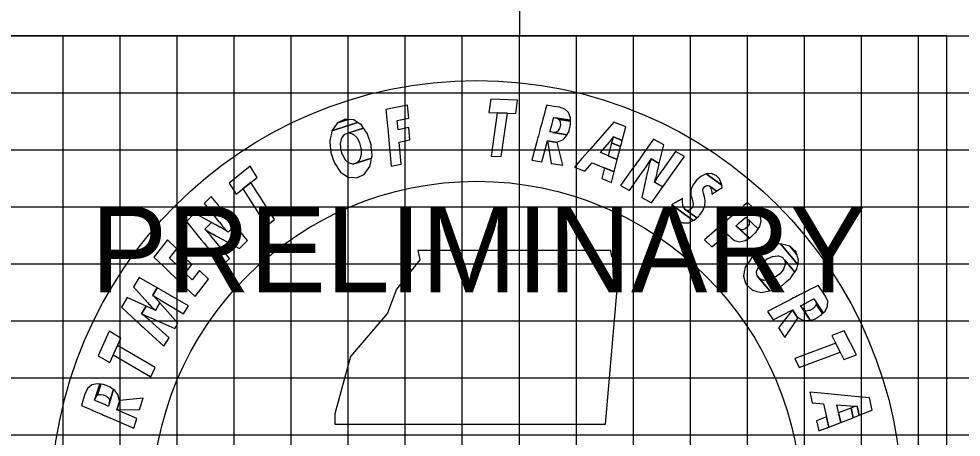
# Model space of a CAD drawing. Extents: x -10 to 342, y -5 to 215.
# Drawn here: x 313.22 to 329.75, y 194.96 to 202.3 of the extents above; entities that cross this region are included whole.
import ezdxf

# ---------------------------------------------------------------- set-up
doc = ezdxf.new("R2010")
doc.units = 0
for name, color, linetype in [('SHEET_CONSULTANT_STAMP', 7, 'Continuous'), ('SHEET_LOGO', 7, 'Continuous'), ('SHEET_LOGO_BG', 7, 'Continuous'), ('SHEET_PRELIM', 7, 'Continuous'), ('SHEET_PROJ_NUMBER', 7, 'Continuous'), ('XS_SHEET_MAJOR_GRIDS', 7, 'Continuous'), ('XS_SHEET_MEDIUM_GRIDS', 7, 'Continuous'), ('XS_SHEET_MINOR_GRIDS', 7, 'Continuous')]:
    doc.layers.add(name, color=color, linetype=linetype)

msp = doc.modelspace()

# ---------------------------------------------------------------- linework, layer by layer
at = {"layer": 'SHEET_CONSULTANT_STAMP'}
msp.add_lwpolyline([(313, 185.5), (329.5, 185.5), (329.5, 202), (313, 202)], close=True, dxfattribs=at)
at = {"layer": 'SHEET_LOGO'}
for points in [[(321.499, 200.886), (321.465, 200.655), (321.937, 200.637), (321.97, 200.868)], [(319.717, 200.101), (319.753, 199.713), (319.928, 199.748), (319.892, 200.136), (320.082, 200.175), (320.062, 200.389), (319.872, 200.351), (319.856, 200.515), (320.06, 200.556), (320.039, 200.785), (319.661, 200.709), (319.682, 200.48), (319.697, 200.315)], [(322.318, 200.184), (322.218, 199.815), (322.394, 199.787), (322.493, 200.157), (322.665, 200.129), (322.662, 200.142), (322.702, 200.15), (322.761, 200.176), (322.824, 200.238), (322.837, 200.264), (322.535, 200.312), (322.537, 200.319), (322.544, 200.345), (322.553, 200.38), (322.557, 200.395), (322.574, 200.456), (322.574, 200.456), (322.586, 200.501), (322.585, 200.501), (322.589, 200.512), (322.598, 200.548), (322.602, 200.563), (322.603, 200.566), (322.897, 200.519), (322.896, 200.561), (322.862, 200.652), (322.797, 200.714), (322.702, 200.745), (322.605, 200.761), (322.478, 200.781), (322.478, 200.781), (322.474, 200.765), (322.461, 200.715), (322.439, 200.634), (322.428, 200.594), (322.427, 200.591), (322.423, 200.576), (322.413, 200.54), (322.41, 200.529), (322.398, 200.484), (322.382, 200.423), (322.378, 200.408), (322.368, 200.373), (322.361, 200.347), (322.359, 200.339), (322.352, 200.313), (322.334, 200.243), (322.324, 200.209), (322.321, 200.197)], [(318.771, 200.416), (318.713, 200.334), (319.16, 200.481), (319.097, 200.523), (318.996, 200.531), (318.809, 200.47)], [(318.946, 200.535), (318.81, 200.47), (318.996, 200.531), (318.946, 200.535)], [(321.614, 200.649), (321.504, 199.89), (321.683, 199.883), (321.793, 200.643)], [(322.635, 200.304), (322.59, 200.303), (322.837, 200.264), (322.841, 200.271), (322.854, 200.296), (322.872, 200.329), (322.875, 200.345), (322.889, 200.406), (322.899, 200.451), (322.898, 200.463), (322.898, 200.5), (322.7, 200.532), (322.719, 200.491), (322.719, 200.48), (322.721, 200.433), (322.704, 200.372), (322.695, 200.357), (322.674, 200.325)], [(322.662, 200.554), (322.7, 200.532), (322.898, 200.5), (322.897, 200.517), (322.897, 200.519), (322.629, 200.562)], [(319.098, 199.512), (319.147, 199.508), (319.283, 199.573), (319.32, 199.625), (319.379, 199.708), (319.394, 199.783), (319.409, 199.853), (319.083, 199.745), (319.082, 199.746), (319.018, 199.762), (319.01, 199.763), (319.008, 199.765), (318.945, 199.823), (318.944, 199.825), (318.942, 199.829), (318.896, 199.914), (318.895, 199.917), (318.894, 199.922), (318.869, 200.012), (318.868, 200.017), (318.868, 200.022), (318.864, 200.12), (318.865, 200.124), (318.866, 200.125), (318.888, 200.212), (318.888, 200.212), (318.896, 200.222), (318.94, 200.274), (319.009, 200.297), (319.266, 200.381), (319.23, 200.435), (319.16, 200.481), (318.713, 200.334), (318.698, 200.26), (318.683, 200.19), (318.683, 200.189), (318.675, 200.15), (318.676, 200.143), (318.676, 200.142), (318.683, 200.065), (318.683, 200.064), (318.683, 200.06), (318.692, 199.964), (318.692, 199.96), (318.693, 199.954), (318.722, 199.866), (318.724, 199.861), (318.725, 199.858), (318.756, 199.768), (318.757, 199.764), (318.758, 199.762), (318.802, 199.698), (318.804, 199.696), (318.806, 199.692), (318.827, 199.662), (318.827, 199.661), (318.863, 199.608), (318.932, 199.561), (318.996, 199.519)], [(319.194, 199.819), (319.151, 199.768), (319.409, 199.853), (319.417, 199.893), (319.417, 199.897), (319.417, 199.9), (319.41, 199.976), (319.41, 199.978), (319.41, 199.978), (319.409, 199.982), (319.401, 200.08), (319.401, 200.083), (319.4, 200.089), (319.37, 200.177), (319.369, 200.182), (319.367, 200.186), (319.337, 200.275), (319.336, 200.279), (319.335, 200.28), (319.292, 200.344), (319.291, 200.345), (319.287, 200.351), (319.267, 200.381), (319.266, 200.381), (319.009, 200.297), (319.009, 200.296), (319.07, 200.279), (319.082, 200.276), (319.083, 200.276), (319.148, 200.218), (319.148, 200.217), (319.15, 200.213), (319.196, 200.13), (319.197, 200.125), (319.198, 200.12), (319.222, 200.03), (319.223, 200.025), (319.223, 200.021), (319.226, 199.922), (319.225, 199.918), (319.224, 199.915), (319.202, 199.829), (319.199, 199.825)], [(323.099, 199.846), (322.968, 199.697), (323.148, 199.622), (323.279, 199.771), (323.662, 199.612), (323.718, 199.828), (323.426, 199.95), (323.579, 200.133), (323.582, 200.136), (323.616, 200.181), (323.617, 200.182), (323.651, 200.229), (323.805, 200.165), (323.866, 200.401), (323.66, 200.487), (323.492, 200.295), (323.453, 200.25), (323.452, 200.249), (323.414, 200.206), (323.411, 200.203), (323.253, 200.022)], [(323.632, 200.174), (323.617, 200.122), (323.776, 200.055), (323.79, 200.108), (323.791, 200.109), (323.805, 200.165), (323.651, 200.229), (323.632, 200.175)], [(323.975, 199.652), (323.776, 199.373), (323.931, 199.285), (324.128, 199.566), (324.128, 199.566), (324.177, 199.635), (324.183, 199.644), (324.222, 199.699), (324.224, 199.702), (324.262, 199.758), (324.268, 199.767), (324.31, 199.839), (324.455, 199.757), (324.533, 200.088), (324.356, 200.187), (324.166, 199.92), (324.117, 199.852), (324.111, 199.843), (324.071, 199.787), (324.069, 199.785), (324.03, 199.73), (324.024, 199.721)], [(322.493, 200.157), (322.561, 199.761), (322.762, 199.729), (322.665, 200.129)], [(323.616, 200.118), (323.556, 199.896), (323.718, 199.828), (323.775, 200.051), (323.776, 200.055), (323.617, 200.122)], [(319.151, 199.768), (319.083, 199.745), (319.409, 199.853), (319.409, 199.853)], [(324.226, 199.511), (324.146, 199.164), (324.317, 199.068), (324.516, 199.347), (324.369, 199.43), (324.395, 199.512), (324.399, 199.522), (324.415, 199.59), (324.416, 199.594), (324.432, 199.662), (324.434, 199.673), (324.455, 199.757), (324.31, 199.839), (324.284, 199.757), (324.28, 199.747), (324.264, 199.679), (324.263, 199.676), (324.248, 199.607), (324.245, 199.596)], [(324.411, 199.502), (324.369, 199.43), (324.516, 199.347), (324.564, 199.416), (324.571, 199.425), (324.61, 199.48), (324.612, 199.483), (324.651, 199.538), (324.658, 199.547), (324.897, 199.883), (324.741, 199.97), (324.503, 199.634), (324.496, 199.625), (324.457, 199.57), (324.455, 199.567), (324.417, 199.512)], [(316.91, 199.416), (317.035, 199.22), (317.404, 199.514), (317.279, 199.711)], [(323.495, 199.682), (323.447, 199.497), (323.615, 199.428), (323.662, 199.612)], [(324.96, 198.931), (324.911, 198.95), (325.112, 198.804), (325.122, 198.813), (325.128, 198.818), (325.145, 198.831), (325.152, 198.841), (325.162, 198.854), (325.184, 198.883), (325.209, 198.915), (325.213, 198.92), (325.225, 198.946), (325.239, 198.978), (325.254, 199.01), (325.255, 199.022), (325.261, 199.093), (325.26, 199.103), (325.247, 199.175), (325.228, 199.239), (325.228, 199.24), (325.22, 199.284), (325.227, 199.324), (325.23, 199.328), (325.251, 199.353), (325.251, 199.353), (325.252, 199.355), (325.256, 199.357), (325.29, 199.375), (325.305, 199.372), (325.305, 199.372), (325.329, 199.368), (325.459, 199.273), (325.502, 199.3), (325.555, 199.333), (325.55, 199.377), (325.277, 199.577), (325.244, 199.561), (325.184, 199.532), (325.148, 199.5), (325.14, 199.493), (325.135, 199.489), (325.108, 199.466), (325.105, 199.463), (325.103, 199.461), (325.084, 199.434), (325.082, 199.431), (325.06, 199.401), (325.042, 199.376), (325.042, 199.375), (325.028, 199.335), (325.011, 199.285), (325.011, 199.277), (325.011, 199.2), (325.015, 199.185), (325.029, 199.132), (325.044, 199.078), (325.049, 199.04), (325.05, 199.032), (325.039, 198.989), (325.015, 198.962), (325.005, 198.949), (324.991, 198.944), (324.969, 198.934)], [(325.31, 199.579), (325.277, 199.576), (325.55, 199.377), (325.546, 199.405), (325.519, 199.474), (325.515, 199.483), (325.454, 199.55), (325.454, 199.55), (325.391, 199.574), (325.371, 199.582)], [(317.152, 199.313), (317.564, 198.666), (317.705, 198.778), (317.292, 199.425)], [(325.374, 199.263), (325.377, 199.22), (325.407, 199.239), (325.409, 199.241), (325.413, 199.243), (325.444, 199.262), (325.45, 199.266), (325.449, 199.266), (325.459, 199.273), (325.329, 199.368), (325.358, 199.333), (325.361, 199.323), (325.373, 199.272), (325.374, 199.267)], [(316.834, 198.614), (316.893, 198.554), (317.011, 198.674), (316.958, 198.739), (316.951, 198.747), (316.908, 198.8), (316.906, 198.802), (316.863, 198.855), (316.856, 198.863), (316.595, 199.182), (316.469, 199.055), (316.731, 198.736), (316.738, 198.728), (316.781, 198.676), (316.783, 198.673), (316.827, 198.622)], [(324.722, 198.8), (324.79, 198.746), (324.803, 198.741), (324.874, 198.715), (324.902, 198.716), (324.972, 198.72), (324.991, 198.729), (325.052, 198.759), (324.673, 199.036), (324.669, 198.965), (324.673, 198.94), (324.683, 198.877), (324.701, 198.841)], [(324.688, 199.044), (324.673, 199.036), (325.052, 198.759), (325.068, 198.766), (325.112, 198.804), (324.911, 198.95), (324.888, 198.984), (324.875, 199.003), (324.87, 199.032), (324.867, 199.049), (324.864, 199.072), (324.864, 199.117), (324.865, 199.142), (324.845, 199.131), (324.81, 199.112), (324.794, 199.103), (324.782, 199.097), (324.762, 199.085), (324.755, 199.081), (324.742, 199.074)], [(325.509, 198.648), (325.246, 198.42), (325.376, 198.299), (325.639, 198.527), (325.674, 198.495), (325.715, 198.457), (325.775, 198.409), (325.858, 198.385), (325.96, 198.408), (326.032, 198.45), (325.799, 198.667), (325.799, 198.667), (325.803, 198.67), (325.821, 198.685), (325.824, 198.688), (325.854, 198.715), (325.897, 198.751), (325.919, 198.771), (325.935, 198.784), (325.96, 198.806), (325.969, 198.814), (325.971, 198.815), (326.19, 198.611), (326.217, 198.651), (326.243, 198.751), (326.227, 198.842), (326.167, 198.921), (326.095, 198.988), (326.001, 199.075), (326.001, 199.075), (325.988, 199.064), (325.946, 199.027), (325.877, 198.968), (325.841, 198.936), (325.839, 198.935), (325.83, 198.927), (325.805, 198.905), (325.789, 198.892), (325.767, 198.872), (325.725, 198.836), (325.694, 198.809), (325.691, 198.806), (325.674, 198.791), (325.669, 198.788), (325.669, 198.788), (325.609, 198.735), (325.543, 198.678), (325.514, 198.653), (325.509, 198.649)], [(316.575, 198.232), (316.793, 197.966), (316.918, 198.094), (316.699, 198.357), (316.699, 198.357), (316.645, 198.422), (316.638, 198.43), (316.595, 198.482), (316.593, 198.485), (316.549, 198.536), (316.542, 198.545), (316.483, 198.604), (316.6, 198.722), (316.302, 198.885), (316.159, 198.74), (316.367, 198.486), (316.42, 198.421), (316.427, 198.413), (316.47, 198.36), (316.472, 198.358), (316.515, 198.306), (316.522, 198.297)], [(316.777, 198.437), (317.091, 198.268), (317.229, 198.408), (317.011, 198.674), (316.893, 198.554), (316.821, 198.6), (316.812, 198.607), (316.751, 198.64), (316.748, 198.642), (316.686, 198.675), (316.676, 198.681), (316.6, 198.722), (316.483, 198.604), (316.555, 198.558), (316.564, 198.552), (316.626, 198.518), (316.628, 198.516), (316.69, 198.483), (316.7, 198.478)], [(325.917, 198.596), (325.875, 198.603), (326.037, 198.453), (326.057, 198.465), (326.061, 198.467), (326.09, 198.495), (326.13, 198.534), (326.152, 198.554), (326.163, 198.571), (326.182, 198.599), (326.189, 198.609), (326.19, 198.611), (325.994, 198.793), (326.017, 198.769), (326.034, 198.737), (326.033, 198.693), (326.022, 198.675), (326.007, 198.649), (325.964, 198.612), (325.921, 198.597)], [(325.842, 198.627), (325.812, 198.655), (326.032, 198.45), (326.032, 198.45), (326.037, 198.453), (325.875, 198.603)], [(316.151, 197.577), (316.311, 197.423), (316.547, 197.727), (316.387, 197.881), (316.26, 197.718), (316.14, 197.833), (316.258, 197.985), (316.102, 198.135), (315.984, 197.984), (315.866, 198.097), (315.992, 198.26), (315.826, 198.42), (315.59, 198.116), (315.756, 197.956), (315.874, 197.843), (316.031, 197.692)], [(323.761, 198.093), (323.623, 198.119), (323.606, 198.231), (320.218, 198.231), (320.252, 198.067), (319.848, 197.551), (319.685, 197.13), (319.04, 196.373), (318.764, 195.367), (318.764, 195.186), (323.512, 195.186)], [(325.961, 197.684), (325.977, 197.636), (326.088, 197.534), (326.15, 197.52), (326.249, 197.496), (326.324, 197.51), (326.394, 197.523), (326.173, 197.785), (326.173, 197.786), (326.163, 197.851), (326.162, 197.859), (326.163, 197.862), (326.193, 197.942), (326.195, 197.944), (326.197, 197.947), (326.259, 198.021), (326.261, 198.023), (326.266, 198.027), (326.34, 198.083), (326.344, 198.086), (326.348, 198.088), (326.438, 198.128), (326.442, 198.128), (326.444, 198.128), (326.531, 198.141), (326.532, 198.141), (326.544, 198.137), (326.609, 198.116), (326.656, 198.06), (326.831, 197.853), (326.867, 197.907), (326.884, 197.989), (326.58, 198.349), (326.505, 198.335), (326.435, 198.322), (326.435, 198.322), (326.394, 198.314), (326.388, 198.311), (326.388, 198.311), (326.319, 198.276), (326.318, 198.275), (326.314, 198.273), (326.229, 198.229), (326.225, 198.227), (326.22, 198.225), (326.149, 198.164), (326.145, 198.161), (326.143, 198.158), (326.071, 198.096), (326.068, 198.094), (326.066, 198.092), (326.023, 198.027), (326.022, 198.025), (326.019, 198.021), (325.999, 197.991), (325.999, 197.991), (325.963, 197.937), (325.946, 197.855), (325.93, 197.78)], [(326.677, 198.325), (326.58, 198.349), (326.884, 197.989), (326.899, 198.063), (326.868, 198.16), (326.742, 198.31)], [(326.854, 198.208), (326.742, 198.31), (326.868, 198.16), (326.854, 198.208)], [(326.283, 197.71), (326.22, 197.73), (326.395, 197.523), (326.435, 197.53), (326.438, 197.532), (326.441, 197.533), (326.509, 197.568), (326.511, 197.569), (326.511, 197.569), (326.515, 197.571), (326.601, 197.615), (326.605, 197.617), (326.61, 197.62), (326.68, 197.68), (326.684, 197.684), (326.688, 197.686), (326.759, 197.747), (326.762, 197.75), (326.763, 197.751), (326.806, 197.816), (326.806, 197.816), (326.81, 197.822), (326.831, 197.853), (326.831, 197.853), (326.656, 198.06), (326.656, 198.06), (326.663, 197.997), (326.664, 197.985), (326.664, 197.984), (326.635, 197.902), (326.634, 197.901), (326.632, 197.898), (326.571, 197.824), (326.568, 197.822), (326.564, 197.818), (326.488, 197.763), (326.484, 197.76), (326.481, 197.758), (326.39, 197.719), (326.385, 197.718), (326.383, 197.718), (326.295, 197.706), (326.29, 197.707)], [(315.599, 197.195), (315.615, 197.18), (315.695, 197.314), (315.681, 197.331), (315.68, 197.33), (315.676, 197.336), (315.674, 197.338), (315.644, 197.372), (315.638, 197.378), (315.638, 197.378), (315.629, 197.389), (315.629, 197.389), (315.627, 197.391), (315.626, 197.392), (315.625, 197.393), (315.625, 197.393), (315.589, 197.429), (315.585, 197.432), (315.569, 197.449), (315.647, 197.579), (315.333, 197.761), (315.232, 197.592), (315.486, 197.311), (315.502, 197.293), (315.505, 197.289), (315.54, 197.252), (315.541, 197.251), (315.542, 197.25), (315.544, 197.248), (315.554, 197.238), (315.559, 197.232), (315.592, 197.201), (315.594, 197.2)], [(326.22, 197.73), (326.173, 197.785), (326.394, 197.523), (326.395, 197.523)], [(315.719, 197.354), (316.109, 197.122), (316.194, 197.262), (315.801, 197.49), (315.783, 197.501), (315.777, 197.504), (315.775, 197.505), (315.775, 197.505), (315.737, 197.527), (315.73, 197.531), (315.719, 197.538), (315.716, 197.539), (315.715, 197.54), (315.713, 197.541), (315.671, 197.565), (315.667, 197.568), (315.647, 197.579), (315.569, 197.449), (315.588, 197.436), (315.592, 197.433), (315.633, 197.407), (315.634, 197.406), (315.635, 197.405), (315.638, 197.404), (315.649, 197.397), (315.656, 197.392), (315.693, 197.37), (315.695, 197.368), (315.701, 197.365)], [(326.694, 197.339), (326.355, 197.163), (326.452, 197.015), (326.792, 197.191), (326.888, 197.045), (326.896, 197.056), (326.927, 197.032), (326.987, 197.006), (327.075, 197.002), (327.103, 197.009), (326.934, 197.265), (326.941, 197.268), (326.966, 197.281), (326.997, 197.297), (327.011, 197.304), (327.068, 197.333), (327.068, 197.333), (327.109, 197.355), (327.108, 197.355), (327.119, 197.36), (327.152, 197.377), (327.166, 197.384), (327.168, 197.385), (327.332, 197.137), (327.363, 197.166), (327.406, 197.253), (327.409, 197.343), (327.368, 197.433), (327.314, 197.516), (327.243, 197.623), (327.243, 197.623), (327.229, 197.615), (327.182, 197.591), (327.107, 197.553), (327.071, 197.534), (327.068, 197.532), (327.054, 197.525), (327.021, 197.508), (327.011, 197.503), (326.97, 197.482), (326.914, 197.452), (326.899, 197.445), (326.868, 197.429), (326.844, 197.416), (326.837, 197.413), (326.812, 197.4), (326.748, 197.367), (326.717, 197.351), (326.705, 197.345)], [(315.425, 196.865), (315.766, 196.551), (315.855, 196.699), (315.512, 197.009), (315.496, 197.023), (315.49, 197.028), (315.49, 197.028), (315.488, 197.029), (315.488, 197.029), (315.455, 197.058), (315.449, 197.063), (315.438, 197.072), (315.436, 197.074), (315.435, 197.075), (315.434, 197.076), (315.395, 197.106), (315.391, 197.109), (315.373, 197.123), (315.453, 197.257), (315.12, 197.408), (315.019, 197.239), (315.291, 196.987), (315.308, 196.972), (315.312, 196.968), (315.349, 196.935), (315.35, 196.934), (315.351, 196.933), (315.353, 196.93), (315.363, 196.921), (315.369, 196.916), (315.402, 196.886), (315.404, 196.884), (315.409, 196.879)], [(327.199, 197.334), (327.208, 197.291), (327.319, 197.124), (327.33, 197.135), (327.332, 197.137), (327.183, 197.364)], [(315.535, 197.048), (315.955, 196.865), (316.011, 196.958), (315.695, 197.314), (315.615, 197.18), (315.596, 197.189), (315.589, 197.192), (315.587, 197.194), (315.548, 197.213), (315.541, 197.216), (315.529, 197.222), (315.526, 197.224), (315.524, 197.224), (315.523, 197.225), (315.479, 197.245), (315.474, 197.248), (315.453, 197.257), (315.373, 197.123), (315.393, 197.114), (315.398, 197.111), (315.442, 197.09), (315.444, 197.089), (315.445, 197.089), (315.448, 197.088), (315.46, 197.082), (315.467, 197.079), (315.507, 197.061), (315.509, 197.06), (315.516, 197.057)], [(326.996, 197.185), (326.965, 197.218), (327.103, 197.009), (327.111, 197.011), (327.139, 197.018), (327.175, 197.028), (327.188, 197.036), (327.243, 197.067), (327.283, 197.09), (327.292, 197.098), (327.319, 197.124), (327.208, 197.291), (327.191, 197.25), (327.183, 197.242), (327.15, 197.209), (327.093, 197.18), (327.076, 197.177), (327.038, 197.17)], [(326.792, 197.191), (326.545, 196.874), (326.658, 196.704), (326.888, 197.045)], [(314.613, 196.384), (314.815, 196.266), (315.008, 196.696), (314.807, 196.814)], [(327.7, 196.822), (327.482, 196.74), (327.693, 196.319), (327.912, 196.4)], [(314.876, 196.402), (315.538, 196.015), (315.612, 196.179), (314.949, 196.566)], [(327.549, 196.607), (326.83, 196.338), (326.911, 196.177), (327.629, 196.447)], [(314.886, 195.266), (315.236, 195.113), (315.29, 195.283), (314.939, 195.435), (314.991, 195.602), (314.978, 195.601), (314.976, 195.64), (314.959, 195.703), (314.907, 195.774), (314.883, 195.791), (314.792, 195.499), (314.784, 195.502), (314.76, 195.513), (314.727, 195.527), (314.712, 195.534), (314.654, 195.559), (314.654, 195.559), (314.612, 195.577), (314.612, 195.577), (314.601, 195.582), (314.567, 195.597), (314.553, 195.603), (314.55, 195.604), (314.639, 195.888), (314.598, 195.894), (314.503, 195.872), (314.432, 195.818), (314.387, 195.728), (314.357, 195.635), (314.319, 195.512), (314.319, 195.512), (314.334, 195.506), (314.382, 195.485), (314.459, 195.451), (314.497, 195.435), (314.499, 195.434), (314.514, 195.427), (314.548, 195.412), (314.559, 195.408), (314.601, 195.39), (314.659, 195.364), (314.674, 195.358), (314.706, 195.344), (314.731, 195.333), (314.738, 195.33), (314.764, 195.319), (314.83, 195.29), (314.862, 195.276), (314.874, 195.271)], [(314.571, 195.661), (314.598, 195.695), (314.658, 195.886), (314.642, 195.888), (314.639, 195.888), (314.558, 195.629)], [(314.814, 195.597), (314.808, 195.552), (314.883, 195.791), (314.877, 195.796), (314.854, 195.813), (314.824, 195.835), (314.809, 195.841), (314.75, 195.863), (314.707, 195.88), (314.695, 195.881), (314.658, 195.886), (314.598, 195.695), (314.641, 195.707), (314.652, 195.706), (314.699, 195.701), (314.757, 195.676), (314.77, 195.664), (314.799, 195.639)], [(327.293, 195.729), (327.096, 195.748), (327.139, 195.558), (327.337, 195.539), (327.431, 195.134), (327.639, 195.215), (327.568, 195.523), (327.806, 195.505), (327.81, 195.505), (327.866, 195.503), (327.867, 195.503), (327.926, 195.502), (327.963, 195.341), (328.19, 195.428), (328.14, 195.645), (327.887, 195.67), (327.827, 195.676), (327.826, 195.676), (327.769, 195.682), (327.765, 195.682), (327.526, 195.706)], [(314.939, 195.435), (315.34, 195.444), (315.401, 195.638), (314.991, 195.602)], [(327.815, 195.467), (327.6, 195.386), (327.639, 195.215), (327.854, 195.298), (327.858, 195.3), (327.819, 195.468)], [(327.87, 195.486), (327.819, 195.468), (327.858, 195.3), (327.908, 195.319), (327.91, 195.32), (327.963, 195.34), (327.926, 195.502), (327.871, 195.486)], [(327.39, 195.311), (327.213, 195.242), (327.253, 195.066), (327.431, 195.134)]]:
    msp.add_lwpolyline(points, close=True, dxfattribs=at)
for radius in [7.464, 5.697]:
    msp.add_circle((321.25, 193.75), radius, dxfattribs=at)
at = {"layer": 'SHEET_LOGO_BG'}
msp.add_lwpolyline([(313, 185.5), (329.5, 185.5), (329.5, 202), (313, 202)], close=True, dxfattribs=at)
at = {"layer": 'SHEET_PRELIM'}
msp.add_lwpolyline([(313, 185.5), (329.5, 185.5), (329.5, 202), (313, 202)], close=True, dxfattribs=at)
at = {"layer": 'SHEET_PROJ_NUMBER'}
for p, q in [((322, 210), (322, 202)), ((313, 202), (340, 202))]:
    msp.add_line(p, q, dxfattribs=at)
at = {"layer": 'XS_SHEET_MAJOR_GRIDS'}
for p, q in [((320, 0), (320, 202)), ((5, 200), (340, 200))]:
    msp.add_line(p, q, dxfattribs=at)
at = {"layer": 'XS_SHEET_MEDIUM_GRIDS'}
for p, q in [((315, 0), (315, 202)), ((325, 0), (325, 202)), ((5, 195), (340, 195))]:
    msp.add_line(p, q, dxfattribs=at)
at = {"layer": 'XS_SHEET_MINOR_GRIDS'}
for p, q in [((314, 0), (314, 202)), ((316, 0), (316, 202)), ((317, 0), (317, 202)), ((318, 0), (318, 202)), ((319, 0), (319, 202)), ((321, 0), (321, 202)), ((322, 0), (322, 202)), ((323, 0), (323, 202)), ((324, 0), (324, 202)), ((326, 0), (326, 202)), ((327, 0), (327, 202)), ((328, 0), (328, 202)), ((329, 0), (329, 202)), ((5, 201), (340, 201)), ((5, 199), (340, 199)), ((5, 198), (340, 198)), ((5, 197), (340, 197)), ((5, 196), (340, 196))]:
    msp.add_line(p, q, dxfattribs=at)

# ---------------------------------------------------------------- texts
at = {"layer": 'SHEET_PRELIM'}
msp.add_text('PRELIMINARY', height=1.5, dxfattribs=at).set_placement((314.485, 197.5))

doc.saveas('drawing.dxf')
